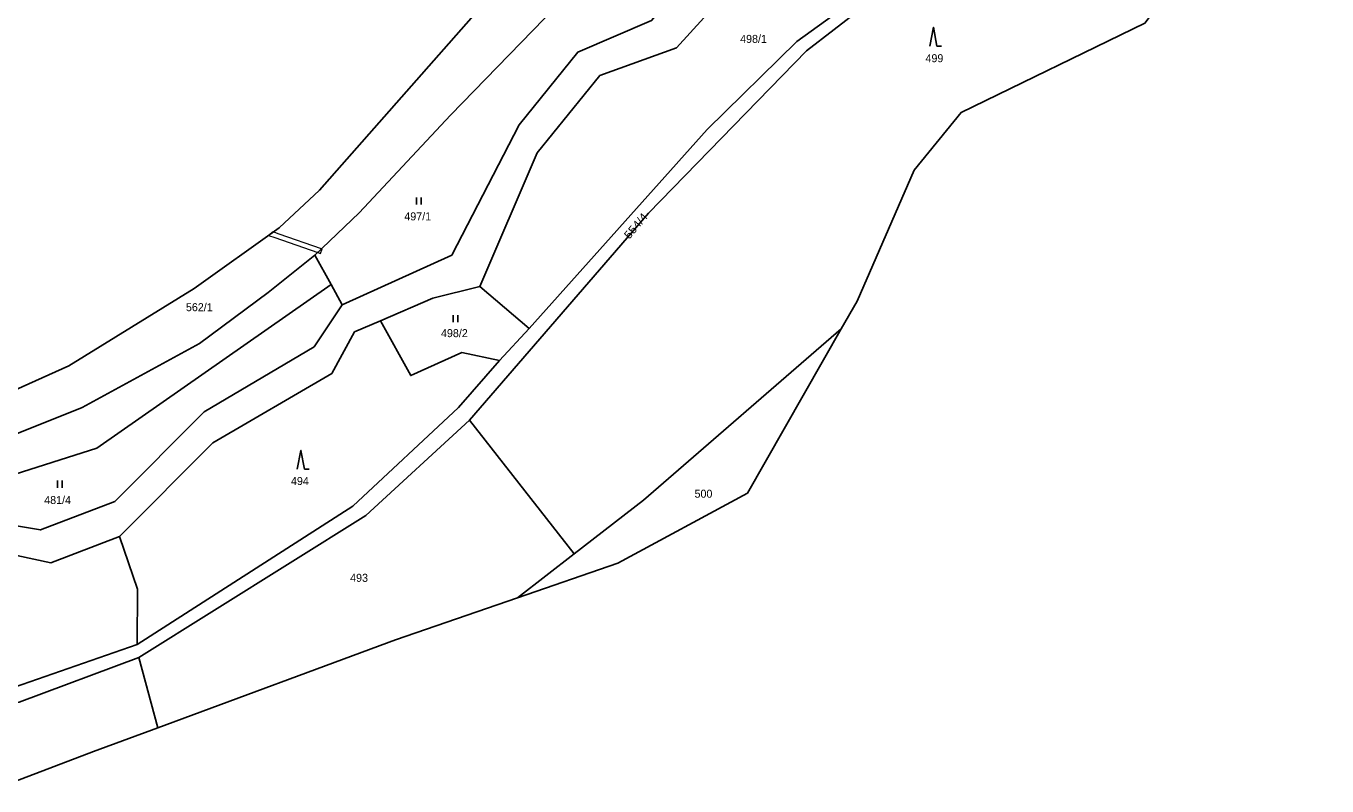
# Model space of a CAD drawing. Extents: x -754445 to -751443, y -1030748 to -1028224.
# Drawn here: x -752878.6 to -752602.2, y -1028889.3 to -1028727.9 of the extents above; entities that cross this region are included whole.
import ezdxf
from ezdxf.enums import TextEntityAlignment as Align

# ---------------------------------------------------------------- set-up
doc = ezdxf.new("R2010")
doc.units = 0
doc.header["$LTSCALE"] = 0.68
for name, color, linetype, lineweight in [('1', 7, 'Continuous', 25), ('13', 7, 'Continuous', 13), ('3', 7, 'Continuous', 25)]:
    doc.layers.add(name, color=color, linetype=linetype, lineweight=lineweight)
doc.layers.add('2', color=7, linetype='Continuous')

msp = doc.modelspace()

# ---------------------------------------------------------------- linework, layer by layer
at = {"layer": '1'}
for p, q in [((-752813.8, -1028782.8), (-752817.23, -1028776.57)), ((-752811.45, -1028787.06), (-752813.8, -1028782.8)), ((-752777.99, -1028798.89), (-752771.67, -1028792.14)), ((-752762.12, -1028839.98), (-752784.35, -1028811.55)), ((-752774.17, -1028849.32), (-752752.87, -1028841.98))]:
    msp.add_line(p, q, dxfattribs=at)
for points in [[(-752604.55, -1028641.14), (-752610.72, -1028650.07), (-752629.83, -1028669.09), (-752660.44, -1028696.62), (-752680.04, -1028709.72), (-752695.17, -1028719.5), (-752712.78, -1028733.15), (-752746.31, -1028767.61), (-752784.35, -1028811.55)], [(-752705.38, -1028792.18), (-752702.03, -1028786.31), (-752689.9, -1028758.48), (-752679.94, -1028746.27), (-752640.88, -1028727.28), (-752602.19, -1028676.58), (-752604.55, -1028641.14)], [(-752715.99, -1028645.08), (-752736.64, -1028676.64), (-752765.51, -1028705.15), (-752816.23, -1028762.72)], [(-752707.98, -1028693.14), (-752718.3, -1028700.81), (-752725.18, -1028715.72), (-752740.37, -1028732.54), (-752756.65, -1028738.41), (-752770, -1028754.8), (-752782.2, -1028783.17), (-752771.67, -1028792.14)], [(-752746.95, -1028703.41), (-752763.49, -1028721.12), (-752788.43, -1028746.82), (-752807.82, -1028767.52), (-752817.23, -1028776.57)], [(-752811.45, -1028787.06), (-752788.16, -1028776.57), (-752773.79, -1028748.89), (-752761.36, -1028733.41), (-752745.7, -1028726.7), (-752734.94, -1028714.07), (-752746.95, -1028703.41)], [(-752771.67, -1028792.14), (-752733.85, -1028749.82), (-752714.83, -1028731.17), (-752697.84, -1028718.84)], [(-752816.23, -1028762.72), (-752824.84, -1028770.74), (-752842.87, -1028783.6)], [(-752817.23, -1028776.57), (-752827.17, -1028784.49), (-752841.76, -1028795.31), (-752866.7, -1028808.91), (-752895.95, -1028820.56), (-752912.35, -1028826.5), (-752935.94, -1028833.24), (-752949.28, -1028833.47)], [(-752842.87, -1028783.6), (-752869.51, -1028800.05), (-752897.89, -1028812.79), (-752936.14, -1028824.21), (-752977.85, -1028823.19), (-752987.76, -1028825.13)], [(-752813.8, -1028782.8), (-752863.56, -1028817.52), (-752940.85, -1028842.12), (-752949.28, -1028833.47)], [(-752782.2, -1028783.17), (-752792.18, -1028785.66), (-752803.31, -1028790.47)], [(-752969.25, -1028838.22), (-752944.55, -1028852.04), (-752939.16, -1028851.86), (-752888.77, -1028832.69), (-752875.53, -1028834.9), (-752859.74, -1028828.82), (-752840.76, -1028809.81), (-752817.4, -1028796.03), (-752811.45, -1028787.06)], [(-752803.31, -1028790.47), (-752808.8, -1028792.84), (-752813.63, -1028801.66), (-752838.9, -1028816.41), (-752858.73, -1028836.29)], [(-752777.99, -1028798.89), (-752785.98, -1028797.22), (-752796.86, -1028802.13), (-752803.31, -1028790.47)], [(-752762.12, -1028839.98), (-752747.4, -1028828.57), (-752705.38, -1028792.18)], [(-752752.87, -1028841.98), (-752725.3, -1028827.06), (-752705.38, -1028792.18)], [(-752855, -1028859.24), (-752809.16, -1028829.87), (-752786.7, -1028808.88), (-752777.99, -1028798.89)], [(-752784.35, -1028811.55), (-752806.43, -1028831.84), (-752854.6, -1028862.01)], [(-752858.73, -1028836.29), (-752873.32, -1028841.91), (-752888.84, -1028838.56), (-752913.41, -1028847.84)], [(-752855, -1028859.24), (-752854.91, -1028847.45), (-752858.73, -1028836.29)], [(-752850.6, -1028876.91), (-752800.08, -1028858.24), (-752774.17, -1028849.32), (-752762.12, -1028839.98)], [(-752903.77, -1028871.6), (-752881.02, -1028868.26), (-752855, -1028859.24)], [(-752854.6, -1028862.01), (-752880.03, -1028871.5), (-752895.33, -1028873.44), (-752923.42, -1028878.46), (-752987.06, -1028904.67)], [(-752906.11, -1028897.87), (-752864.28, -1028881.96), (-752850.6, -1028876.91), (-752854.6, -1028862.01)]]:
    msp.add_lwpolyline(points, dxfattribs=at)
at = {"layer": '13'}
for points in [[(-752824.8, -1028772.05), (-752826.06, -1028771.61), (-752827.07, -1028772.33), (-752825.73, -1028772.79), (-752816.59, -1028775.96), (-752815.79, -1028775.18)], [(-752816.04, -1028776.15), (-752815.71, -1028775.21), (-752815.79, -1028775.18), (-752816.59, -1028775.96)]]:
    msp.add_lwpolyline(points, close=True, dxfattribs=at)
at = {"layer": '3'}
for p, q in [((-752685.06, -1028732.13), (-752684.064, -1028732.13)), ((-752795.641, -1028765.77), (-752795.641, -1028764.27)), ((-752794.64, -1028765.77), (-752794.64, -1028764.27)), ((-752787.831, -1028790.75), (-752787.831, -1028789.25)), ((-752786.83, -1028790.75), (-752786.83, -1028789.25)), ((-752819.46, -1028822.02), (-752818.464, -1028822.02)), ((-752871.921, -1028825.93), (-752871.921, -1028824.43)), ((-752870.92, -1028825.93), (-752870.92, -1028824.43))]:
    msp.add_line(p, q, dxfattribs=at)
for points in [[(-752685.06, -1028732.13), (-752685.81, -1028728.13), (-752686.56, -1028732.13)], [(-752819.46, -1028822.02), (-752820.21, -1028818.02), (-752820.96, -1028822.02)]]:
    msp.add_lwpolyline(points, dxfattribs=at)

# ---------------------------------------------------------------- texts
at = {"layer": '2'}
for s, p in [('498/1', (-752724.03, -1028731.46)), ('499', (-752685.599, -1028735.56)), ('497/1', (-752795.38, -1028769.15)), ('562/1', (-752841.78, -1028788.44)), ('498/2', (-752787.59, -1028793.95)), ('494', (-752820.409, -1028825.35)), ('481/4', (-752871.89, -1028829.39)), ('500', (-752734.669, -1028828.05)), ('493', (-752807.839, -1028845.91))]:
    msp.add_text(s, height=1.7, dxfattribs=at).set_placement(p, align=Align.CENTER)
at = {"layer": '2', "width": 1.1}
msp.add_text('554/4', height=1.7, rotation=50, dxfattribs=at).set_placement((-752748.4028, -1028770.8614), align=Align.CENTER)

doc.saveas('drawing.dxf')
